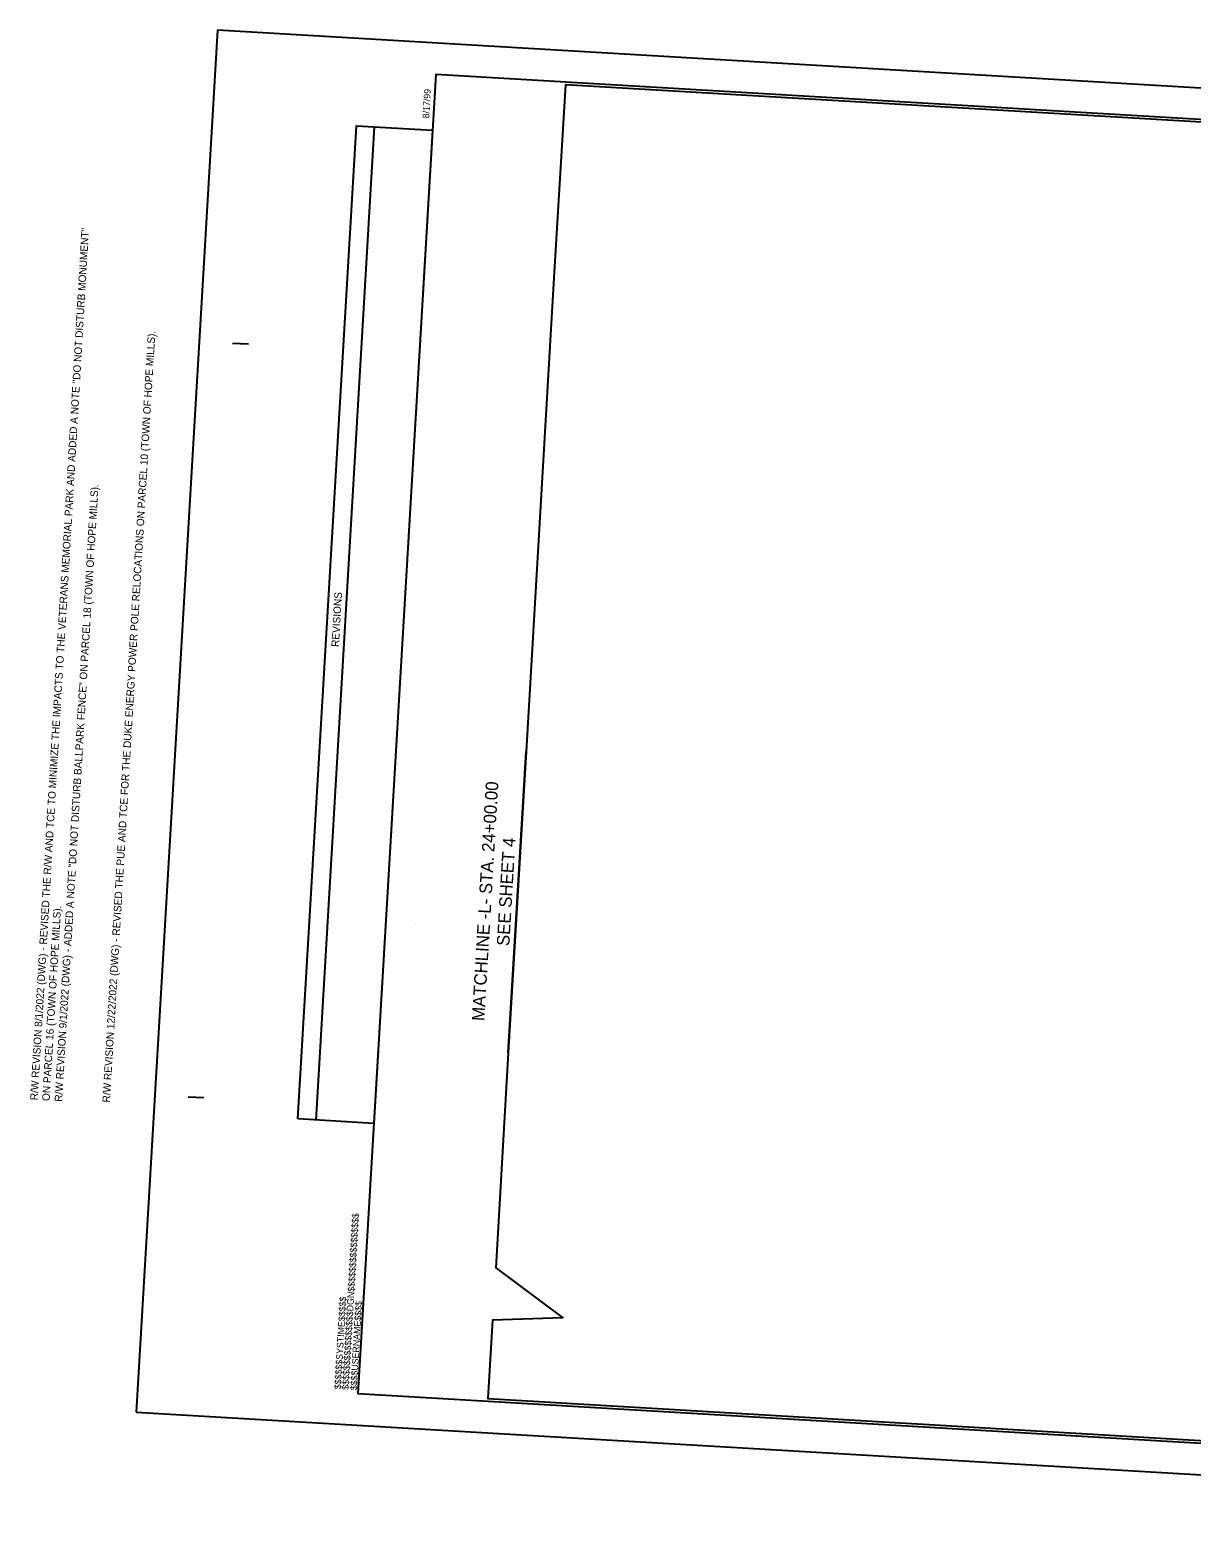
# Model space of a CAD drawing. Extents: x 2012250 to 2014096, y 444445 to 445643.
# Drawn here: x 2012250 to 2013173, y 444445 to 445643 of the extents above; entities that cross this region are included whole.
import ezdxf

# ---------------------------------------------------------------- set-up
doc = ezdxf.new("R2010")
doc.units = 0
for name, color, linetype in [('Exist PHM Road to be Removed Shape', 7, 'Continuous'), ('Matchline', 7, 'Continuous'), ('Matchline Text', 7, 'Continuous'), ('Old_Level_45', 7, 'Continuous'), ('Sheet Block Revision CELL', 7, 'Continuous'), ('Sheet Block System Information CELL', 7, 'Continuous'), ('Sheet Clip Boundary CELL', 7, 'Continuous'), ('Sheet Plot Border Outside CELL', 7, 'Continuous'), ('Sheet Profile Grid Minor CELL', 7, 'Continuous')]:
    doc.layers.add(name, color=color, linetype=linetype)

msp = doc.modelspace()

# ---------------------------------------------------------------- linework, layer by layer
at = {"layer": 'Exist PHM Road to be Removed Shape'}
msp.add_line((2012556.2, 444933.3), (2012556.2, 444933.3), dxfattribs=at)
at = {"layer": 'Matchline'}
msp.add_line((2012629.9, 444830.5), (2012644, 445070), dxfattribs=at)
at = {"layer": 'Old_Level_45'}
for p, q in [((2012410.9, 445394.5), (2012423.4, 445393.8)), ((2012375.6, 444795.5), (2012388.1, 444794.8)), ((2012510.5, 444559.7), (2012510.5, 444559.7)), ((2012510.5, 444559.7), (2012510.5, 444559.7)), ((2012510.5, 444559.7), (2012510.5, 444559.7)), ((2012510.5, 444559.7), (2012510.5, 444559.7)), ((2012510.5, 444559.7), (2012510.5, 444559.7))]:
    msp.add_line(p, q, dxfattribs=at)
msp.add_lwpolyline([(2014069.7, 445519.6), (2012572.3, 445607.9), (2012510.5, 444559.7), (2014007.9, 444471.4)], close=True, dxfattribs=at)
at = {"layer": 'Sheet Block Revision CELL'}
msp.add_line((2012477.2, 444777), (2012523.7, 445566.3), dxfattribs=at)
msp.add_lwpolyline([(2012462.7, 444777.9), (2012509.2, 445567.2), (2012569.7, 445563.6), (2012523.1, 444774.3)], close=True, dxfattribs=at)
at = {"layer": 'Sheet Block System Information CELL'}
msp.add_line((2012510.5, 444559.7), (2012510.5, 444559.7), dxfattribs=at)
at = {"layer": 'Sheet Clip Boundary CELL'}
msp.add_lwpolyline([(2013668.2, 445541.3), (2012675.4, 445599.8), (2012666.5, 445450.9), (2012644, 445070), (2012629.9, 444830.5), (2012620, 444659.5), (2012673.2, 444619.9), (2012617.3, 444618), (2012613.7, 444555.6), (2014006, 444473.5), (2014042, 445083.4), (2013915.8, 445258.4), (2013612.4, 445329.9), (2013616, 445390.9), (2013652.4, 445436.9), (2013664.2, 445474.7)], close=True, dxfattribs=at)
at = {"layer": 'Sheet Plot Border Outside CELL'}
msp.add_lwpolyline([(2012334.3, 444545), (2014031.4, 444445), (2014096.1, 445543.1), (2012399, 445643.1)], close=True, dxfattribs=at)

# ---------------------------------------------------------------- texts
at = {"layer": 'Matchline Text'}
for s, p in [('MATCHLINE -L- STA. 24+00.00', (2012610.9, 444855.5)), ('SEE SHEET 4', (2012630.7, 444915.1))]:
    msp.add_text(s, height=10, rotation=86.6264, dxfattribs=at).set_placement(p)
at = {"layer": 'Old_Level_45'}
msp.add_text('8/17/99', height=5.25, rotation=86.6264, dxfattribs=at).set_placement((2012567, 445572.9))
at = {"layer": 'Sheet Block Revision CELL'}
msp.add_text('REVISIONS', height=6, rotation=86.6264, dxfattribs=at).set_placement((2012495.3, 445152.8))
at = {"layer": 'Sheet Block System Information CELL'}
for s, p in [('$$$$$$$$$$$$$$$$DGN$$$$$$$$$$$$$$$$', (2012503, 444562.5)), ('$$$$$$SYSTIME$$$$$', (2012496.9, 444562.9)), ('$$$$USERNAME$$$$', (2012509.6, 444562.1))]:
    msp.add_text(s, height=5.25, rotation=86.6264, dxfattribs=at).set_placement(p)
at = {"layer": 'Sheet Profile Grid Minor CELL'}
for s, p in [('R/W REVISION 8/1/2022 (DWG) - REVISED THE R/W AND TCE TO MINIMIZE THE IMPACTS TO THE VETERANS MEMORIAL PARK AND ADDED A NOTE "DO NOT DISTURB MONUMENT" ', (2012256, 444792.6)), ('R/W REVISION 12/22/2022 (DWG) - REVISED THE PUE AND TCE FOR THE DUKE ENERGY POWER POLE RELOCATIONS ON PARCEL 10 (TOWN OF HOPE MILLS).', (2012313.4, 444790.8)), ('R/W REVISION 9/1/2022 (DWG) - ADDED A NOTE "DO NOT DISTURB BALLPARK FENCE" ON PARCEL 18 (TOWN OF HOPE MILLS). ', (2012275.4, 444791.4)), ('ON PARCEL 16 (TOWN OF HOPE MILLS).', (2012265.5, 444792))]:
    msp.add_text(s, height=6, rotation=86.6264, dxfattribs=at).set_placement(p)

doc.saveas('drawing.dxf')
